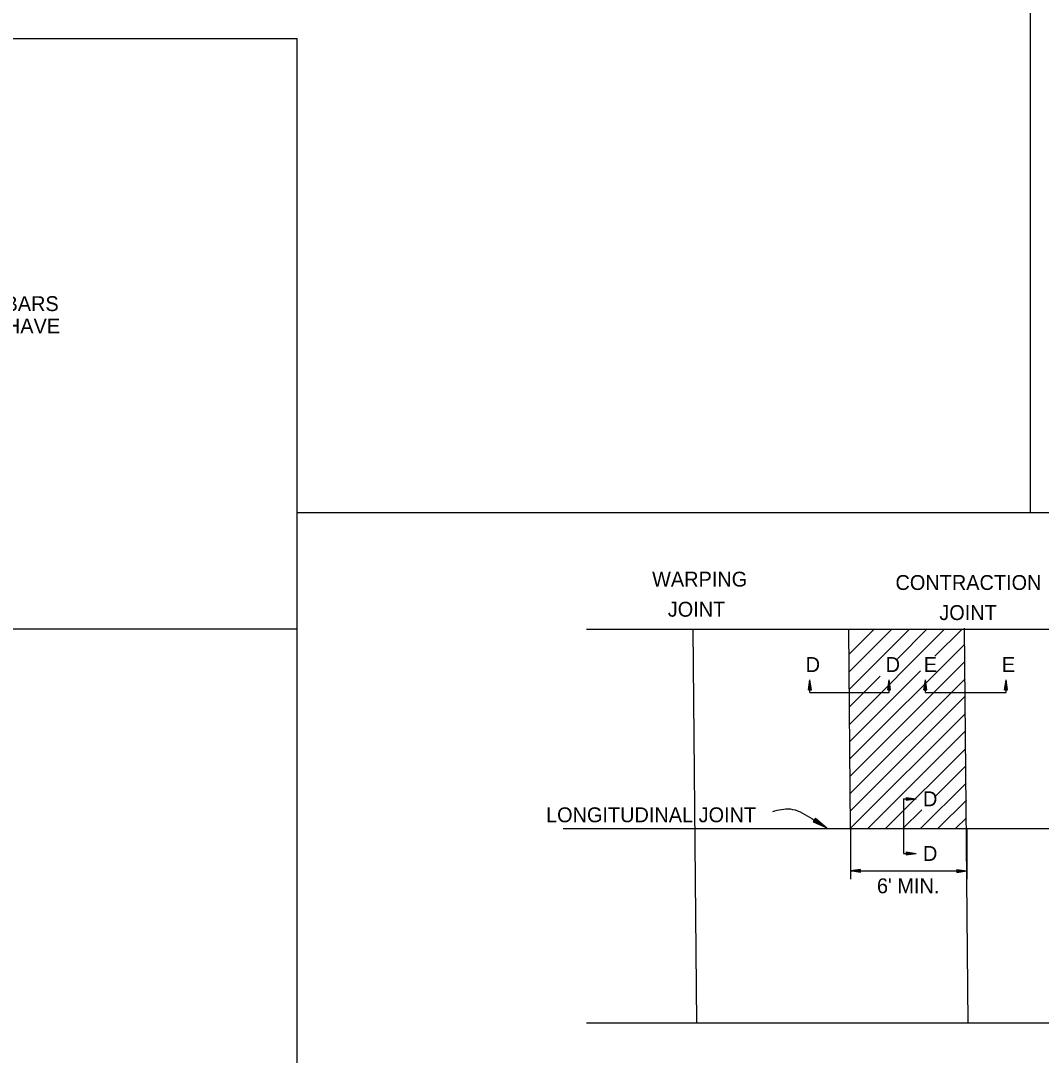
# Model space of a CAD drawing. Extents: x 1375738 to 1375905, y 380661 to 380875.
# Drawn here: x 1375777.18 to 1375810.09, y 380817.52 to 380850.89 of the extents above; entities that cross this region are included whole.
import ezdxf

# ---------------------------------------------------------------- set-up
doc = ezdxf.new("R2010")
doc.units = 0
doc.layers.add('R_Border', color=7, linetype='Continuous')
doc.layers.add('R_Draft', color=7, linetype='Continuous')

msp = doc.modelspace()

# ---------------------------------------------------------------- linework, layer by layer
at = {"layer": 'R_Border'}
for p, q in [((1375809.745, 380835.027), (1375809.745, 380872.783)), ((1375744.419, 380850.32), (1375786.095, 380850.32)), ((1375786.095, 380770.053), (1375786.095, 380850.32)), ((1375786.095, 380835.027), (1375854.78, 380835.027)), ((1375744.419, 380831.274), (1375786.095, 380831.274))]:
    msp.add_line(p, q, dxfattribs=at)
at = {"layer": 'R_Draft'}
for p, q in [((1375807.74, 380818.564), (1375807.618, 380831.296)), ((1375795.429, 380831.261), (1375839.429, 380831.261)), ((1375798.988, 380818.564), (1375798.867, 380831.261)), ((1375803.945, 380824.829), (1375803.883, 380831.261)), ((1375803.891, 380830.444), (1375804.708, 380831.261)), ((1375803.897, 380829.884), (1375805.273, 380831.261)), ((1375803.902, 380829.323), (1375805.839, 380831.261)), ((1375803.913, 380828.203), (1375806.97, 380831.261)), ((1375805.451, 380830.306), (1375806.405, 380831.261)), ((1375806.664, 380830.388), (1375807.537, 380831.261)), ((1375803.923, 380827.082), (1375807.623, 380830.782)), ((1375803.929, 380826.521), (1375807.629, 380830.222)), ((1375802.581, 380829.305), (1375802.629, 380829.625)), ((1375802.629, 380829.225), (1375802.629, 380829.625)), ((1375802.677, 380829.305), (1375802.629, 380829.625)), ((1375803.907, 380828.763), (1375804.897, 380829.753)), ((1375803.918, 380827.642), (1375806.194, 380829.918)), ((1375803.934, 380825.961), (1375807.634, 380829.661)), ((1375805.139, 380829.305), (1375805.187, 380829.625)), ((1375805.187, 380829.225), (1375805.187, 380829.625)), ((1375805.235, 380829.305), (1375805.187, 380829.625)), ((1375806.309, 380829.305), (1375806.357, 380829.625)), ((1375806.357, 380829.225), (1375806.357, 380829.625)), ((1375806.405, 380829.305), (1375806.357, 380829.625)), ((1375808.911, 380829.305), (1375808.959, 380829.625)), ((1375808.959, 380829.225), (1375808.959, 380829.625)), ((1375809.007, 380829.305), (1375808.959, 380829.625)), ((1375802.581, 380829.305), (1375802.677, 380829.305)), ((1375802.589, 380829.305), (1375802.629, 380829.571)), ((1375802.597, 380829.305), (1375802.629, 380829.517)), ((1375802.605, 380829.305), (1375802.629, 380829.463)), ((1375802.613, 380829.305), (1375802.629, 380829.409)), ((1375802.621, 380829.305), (1375802.629, 380829.355)), ((1375802.669, 380829.305), (1375802.629, 380829.571)), ((1375802.661, 380829.305), (1375802.629, 380829.517)), ((1375802.653, 380829.305), (1375802.629, 380829.463)), ((1375802.645, 380829.305), (1375802.629, 380829.409)), ((1375802.637, 380829.305), (1375802.629, 380829.355)), ((1375805.139, 380829.305), (1375805.235, 380829.305)), ((1375805.147, 380829.305), (1375805.187, 380829.571)), ((1375805.155, 380829.305), (1375805.187, 380829.517)), ((1375805.163, 380829.305), (1375805.187, 380829.463)), ((1375805.171, 380829.305), (1375805.187, 380829.409)), ((1375805.179, 380829.305), (1375805.187, 380829.355)), ((1375805.227, 380829.305), (1375805.187, 380829.571)), ((1375805.219, 380829.305), (1375805.187, 380829.517)), ((1375805.211, 380829.305), (1375805.187, 380829.463)), ((1375805.203, 380829.305), (1375805.187, 380829.409)), ((1375805.195, 380829.305), (1375805.187, 380829.355)), ((1375806.309, 380829.305), (1375806.405, 380829.305)), ((1375806.317, 380829.305), (1375806.357, 380829.571)), ((1375806.325, 380829.305), (1375806.357, 380829.517)), ((1375806.333, 380829.305), (1375806.357, 380829.463)), ((1375806.341, 380829.305), (1375806.357, 380829.409)), ((1375806.349, 380829.305), (1375806.357, 380829.355)), ((1375806.397, 380829.305), (1375806.357, 380829.571)), ((1375806.389, 380829.305), (1375806.357, 380829.517)), ((1375806.381, 380829.305), (1375806.357, 380829.463)), ((1375806.372, 380829.305), (1375806.357, 380829.409)), ((1375806.364, 380829.305), (1375806.357, 380829.355)), ((1375808.911, 380829.305), (1375809.007, 380829.305)), ((1375808.919, 380829.305), (1375808.959, 380829.571)), ((1375808.927, 380829.305), (1375808.959, 380829.517)), ((1375808.935, 380829.305), (1375808.959, 380829.463)), ((1375808.943, 380829.305), (1375808.959, 380829.409)), ((1375808.951, 380829.305), (1375808.959, 380829.355)), ((1375808.999, 380829.305), (1375808.959, 380829.571)), ((1375808.991, 380829.305), (1375808.959, 380829.517)), ((1375808.983, 380829.305), (1375808.959, 380829.463)), ((1375808.975, 380829.305), (1375808.959, 380829.409)), ((1375808.967, 380829.305), (1375808.959, 380829.355)), ((1375802.629, 380829.225), (1375805.187, 380829.225)), ((1375803.939, 380825.401), (1375807.639, 380829.101)), ((1375806.357, 380829.225), (1375808.959, 380829.225)), ((1375803.945, 380824.841), (1375807.645, 380828.541)), ((1375804.499, 380824.829), (1375807.65, 380827.981)), ((1375805.065, 380824.829), (1375807.655, 380827.419)), ((1375806.678, 380825.877), (1375807.661, 380826.86)), ((1375806.196, 380824.829), (1375807.666, 380826.3)), ((1375805.653, 380825.791), (1375805.653, 380824.029)), ((1375805.653, 380825.791), (1375806.053, 380825.791)), ((1375805.733, 380825.839), (1375806.053, 380825.791)), ((1375805.733, 380825.839), (1375805.733, 380825.743)), ((1375805.733, 380825.831), (1375805.999, 380825.791)), ((1375805.733, 380825.823), (1375805.944, 380825.791)), ((1375805.733, 380825.815), (1375805.891, 380825.791)), ((1375805.733, 380825.807), (1375805.837, 380825.791)), ((1375805.733, 380825.799), (1375805.783, 380825.791)), ((1375805.733, 380825.743), (1375806.053, 380825.791)), ((1375805.733, 380825.775), (1375805.837, 380825.791)), ((1375805.733, 380825.759), (1375805.944, 380825.791)), ((1375805.733, 380825.751), (1375805.999, 380825.791)), ((1375805.733, 380825.767), (1375805.891, 380825.791)), ((1375805.733, 380825.783), (1375805.783, 380825.791)), ((1375806.761, 380824.829), (1375807.671, 380825.739)), ((1375807.675, 380825.743), (1375807.671, 380825.739)), ((1375805.63, 380824.829), (1375806.242, 380825.441)), ((1375802.807, 380825.172), (1375802.732, 380825.049)), ((1375802.732, 380825.049), (1375803.18, 380824.861)), ((1375802.738, 380825.059), (1375803.111, 380824.903)), ((1375802.745, 380825.07), (1375803.041, 380824.946)), ((1375802.751, 380825.08), (1375802.973, 380824.987)), ((1375802.757, 380825.091), (1375802.903, 380825.029)), ((1375802.764, 380825.101), (1375802.834, 380825.071)), ((1375802.775, 380825.12), (1375802.834, 380825.071)), ((1375802.782, 380825.131), (1375802.903, 380825.029)), ((1375802.788, 380825.141), (1375802.973, 380824.987)), ((1375802.794, 380825.151), (1375803.041, 380824.946)), ((1375802.801, 380825.162), (1375803.111, 380824.903)), ((1375802.807, 380825.172), (1375803.18, 380824.861)), ((1375807.328, 380824.829), (1375807.677, 380825.178)), ((1375794.677, 380824.829), (1375839.429, 380824.829)), ((1375803.945, 380824.829), (1375803.945, 380823.201)), ((1375806.196, 380824.829), (1375839.375, 380824.829)), ((1375807.693, 380824.829), (1375807.693, 380823.201)), ((1375805.653, 380824.029), (1375806.053, 380824.029)), ((1375805.733, 380824.077), (1375806.053, 380824.029)), ((1375805.733, 380824.077), (1375805.733, 380823.981)), ((1375805.733, 380824.069), (1375805.999, 380824.029)), ((1375805.733, 380824.061), (1375805.944, 380824.029)), ((1375805.733, 380824.053), (1375805.891, 380824.029)), ((1375805.733, 380824.045), (1375805.837, 380824.029)), ((1375805.733, 380824.037), (1375805.783, 380824.029)), ((1375805.733, 380823.981), (1375806.053, 380824.029)), ((1375805.733, 380824.014), (1375805.837, 380824.029)), ((1375805.733, 380823.997), (1375805.944, 380824.029)), ((1375805.733, 380823.989), (1375805.999, 380824.029)), ((1375805.733, 380824.005), (1375805.891, 380824.029)), ((1375805.733, 380824.022), (1375805.783, 380824.029)), ((1375804.265, 380823.513), (1375803.945, 380823.465)), ((1375803.945, 380823.465), (1375807.693, 380823.465)), ((1375804.265, 380823.417), (1375803.945, 380823.465)), ((1375804.265, 380823.505), (1375803.999, 380823.465)), ((1375804.265, 380823.425), (1375803.999, 380823.465)), ((1375804.265, 380823.497), (1375804.053, 380823.465)), ((1375804.265, 380823.433), (1375804.053, 380823.465)), ((1375804.265, 380823.489), (1375804.107, 380823.465)), ((1375804.265, 380823.441), (1375804.107, 380823.465)), ((1375804.265, 380823.481), (1375804.161, 380823.465)), ((1375804.265, 380823.449), (1375804.161, 380823.465)), ((1375804.265, 380823.473), (1375804.215, 380823.465)), ((1375804.265, 380823.457), (1375804.215, 380823.465)), ((1375804.265, 380823.417), (1375804.265, 380823.513)), ((1375807.373, 380823.513), (1375807.693, 380823.465)), ((1375807.373, 380823.513), (1375807.373, 380823.417)), ((1375807.373, 380823.505), (1375807.639, 380823.465)), ((1375807.373, 380823.497), (1375807.585, 380823.465)), ((1375807.373, 380823.489), (1375807.531, 380823.465)), ((1375807.373, 380823.481), (1375807.477, 380823.465)), ((1375807.373, 380823.473), (1375807.423, 380823.465)), ((1375807.373, 380823.417), (1375807.693, 380823.465)), ((1375807.373, 380823.449), (1375807.477, 380823.465)), ((1375807.373, 380823.433), (1375807.585, 380823.465)), ((1375807.373, 380823.425), (1375807.639, 380823.465)), ((1375807.373, 380823.441), (1375807.531, 380823.465)), ((1375807.373, 380823.457), (1375807.423, 380823.465)), ((1375795.429, 380818.564), (1375839.223, 380818.564)), ((1375808.942, 380818.564), (1375808.942, 380818.564))]:
    msp.add_line(p, q, dxfattribs=at)
msp.add_spline([(1375801.43, 380825.384), (1375801.993, 380825.465), (1375802.617, 380825.203), (1375803.18, 380824.861)], degree=3, dxfattribs=at)

# ---------------------------------------------------------------- texts
for s, p in [('1 1/4" ROUND STEEL DOWEL BARS', (1375767.545, 380841.525)), ('@ 12" CTRS. DOWEL BAR TO HAVE', (1375767.545, 380840.805)), ('WARPING', (1375797.541, 380832.638)), ('CONTRACTION', (1375805.391, 380832.529)), ('JOINT', (1375798.047, 380831.667)), ('JOINT', (1375806.804, 380831.559)), ('D', (1375802.494, 380829.883)), ('D', (1375805.074, 380829.883)), ('E', (1375806.303, 380829.883)), ('E', (1375808.821, 380829.883)), ('D', (1375806.278, 380825.551)), ('LONGITUDINAL JOINT', (1375794.12, 380825.036)), ('D', (1375806.278, 380823.789)), ("6' MIN.", (1375804.793, 380822.745))]:
    msp.add_text(s, height=0.48, dxfattribs=at).set_placement(p)

doc.saveas('drawing.dxf')
